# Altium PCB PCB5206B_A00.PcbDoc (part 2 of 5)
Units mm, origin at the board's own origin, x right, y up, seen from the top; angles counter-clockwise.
Board outline 115 x 60 mm, 6 copper layers (Top Layer, GND Layer 2, Signal Layer 3, Signal Layer 4, VCC Layer 5, Bottom Layer), stack 1.555 mm thick; 384 components, 267 nets, 1313 pads, 834 vias.
Unrouted connection lines stored in the file: 10.
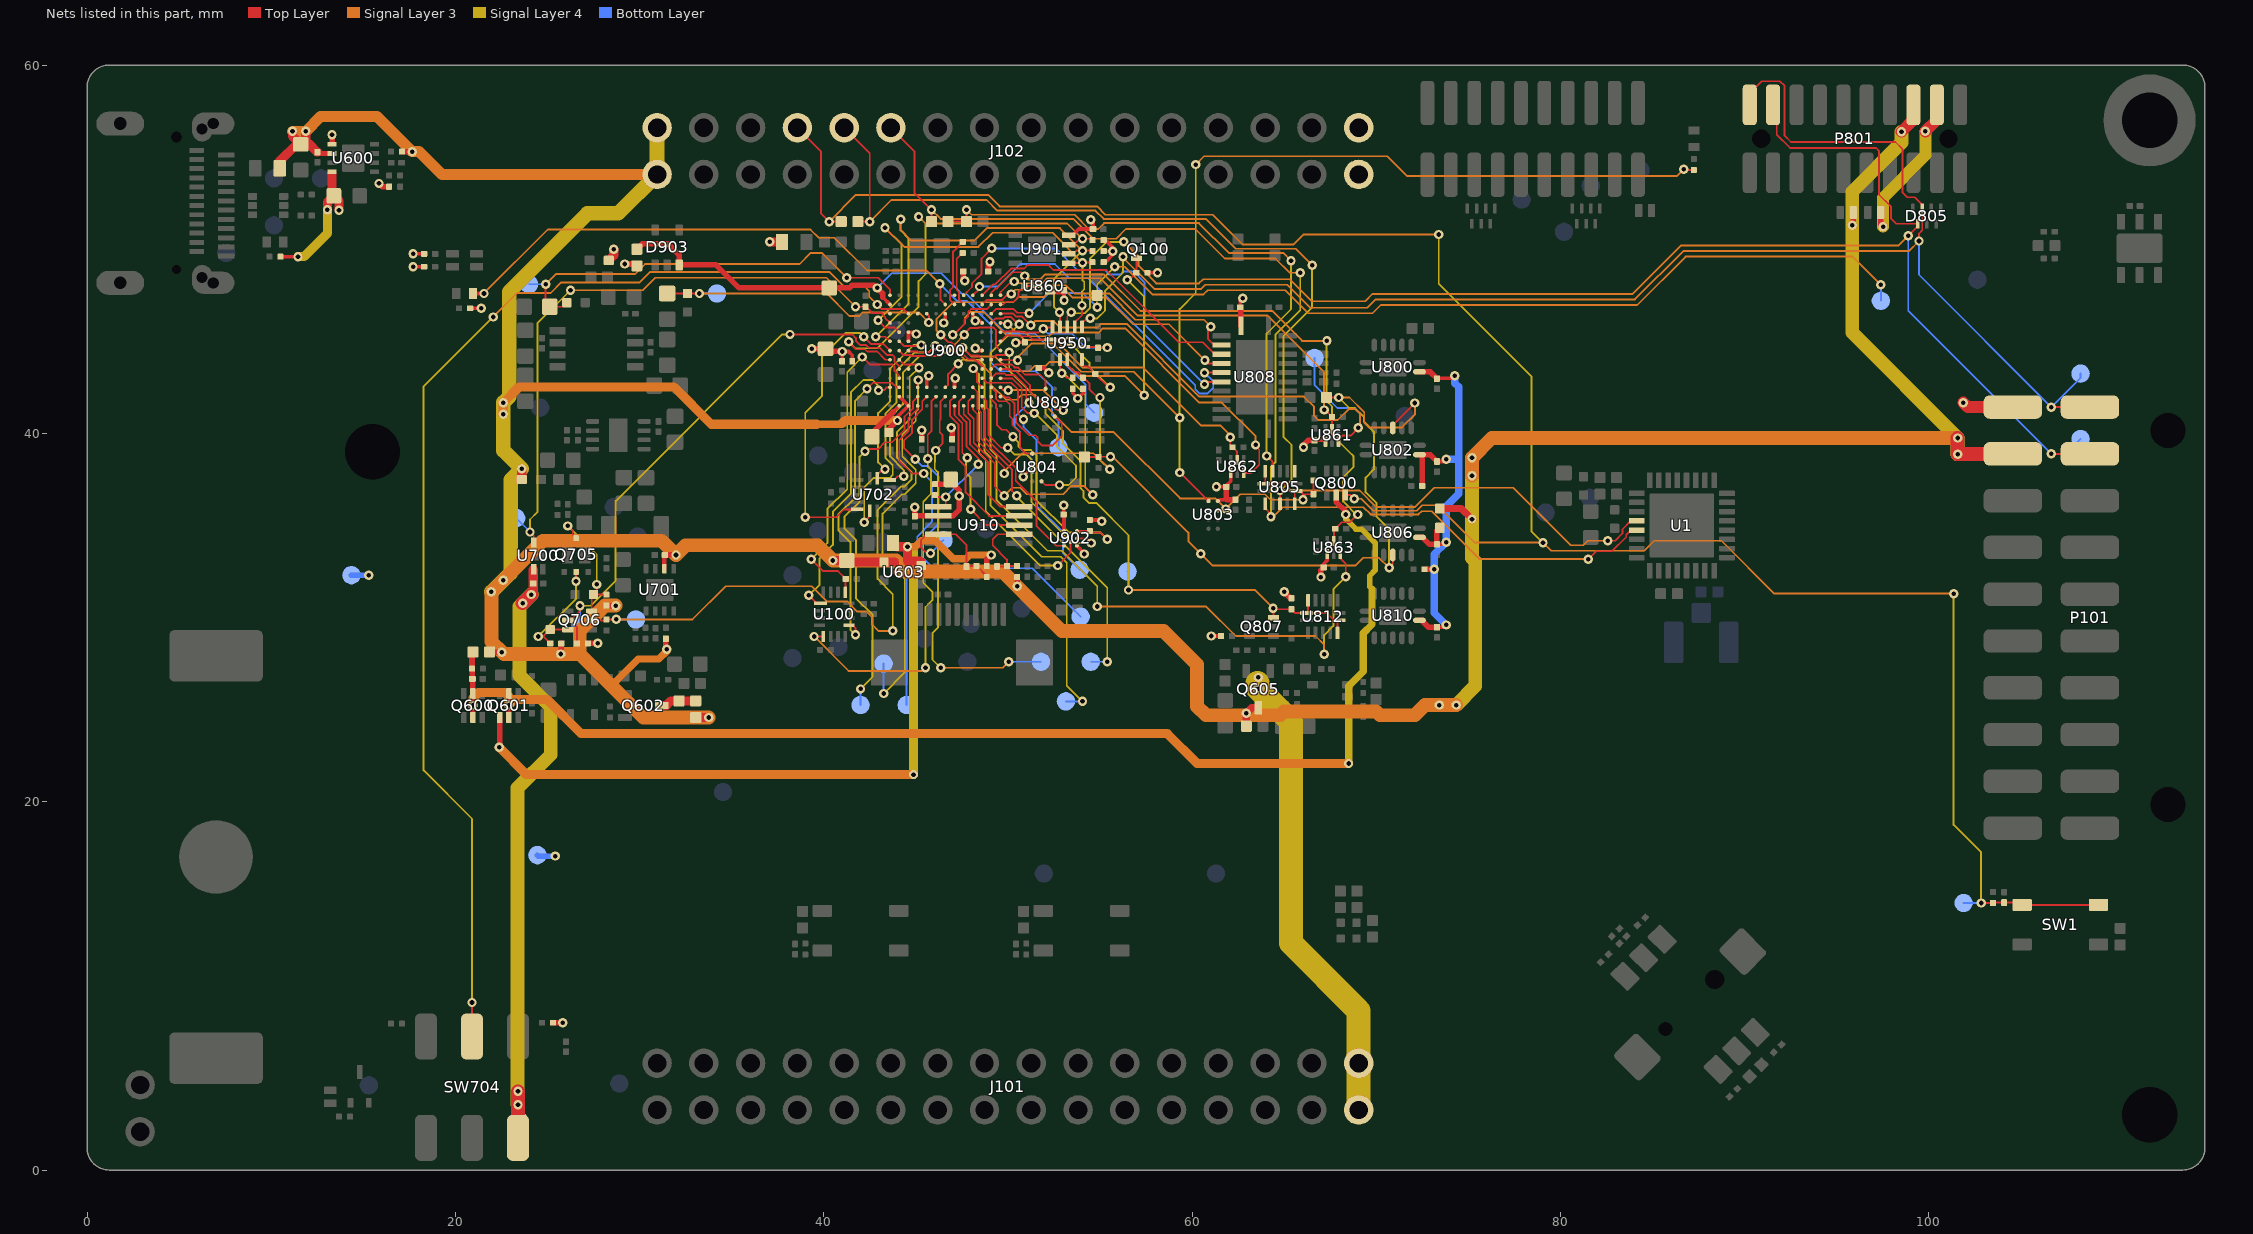
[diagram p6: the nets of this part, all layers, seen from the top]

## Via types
v1: diameter 0.508, hole 0.25, Top Layer to Bottom Layer, tented both sides, 834 vias

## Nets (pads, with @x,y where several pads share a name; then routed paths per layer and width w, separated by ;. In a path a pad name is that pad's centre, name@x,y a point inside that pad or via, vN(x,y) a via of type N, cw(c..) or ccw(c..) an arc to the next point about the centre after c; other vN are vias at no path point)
3V3: C607.1 C807.1 C808.1 C860.1 C862.1 C864.1 C866.1 C907.1 C908.1 C909.1 C910.1 C911.1 C914.1 C921.1 C922.1 C924.1 C925.1 C926.1 C927.1 C951.1 D807.1 J101.31 J101.32 J102.31 J102.32 L704.1 L900.1 P101.20 P801.3 R142.2 R601.2 R756.2 R793.2 R838.2 R840.2 R903.1 R906.2 R907.1 R908.1 R909.1 R912.1 R919.1 R920.1 R928.2 R951.1 R952.1 R982.1 TPJ600.1 TPJ950.1 U600.1 U600.4 U803.A2 U808.1 U860.1 U861.1 U862.1 U863.1 U900.C6 U900.C9 U900.G3 U900.H11 U900.J11 U900.K3 U900.L4 U900.L7 U901.8 U902.A1 U902.E3 U910.2 | length 87.6
  Top Layer w0.2: R903.1@10.5,49.6 v1(11.45,49.6) ; U600.1@13.3,55.7 13.3,55.85 ; v1(17.7,49.05) R919.1@18.3,49.05 ; v1(17.7,49.75) R920.1@18.3,49.75 ; R912.1@20.8,46.8 v1(21.4,46.8) ; C924.1@41,43.925 41,44.325 41.125,44.45 41.35,44.45 41.55,44.25 C925.1@41.55,43.925 ; U900.H11@44.6,45 U900.J11@44.6,45.5 44.925,45.5 v1(45.025,45.4) ; U900.C9@45.6,42.5 45.6,43.025 v1(45.7,43.125) ; v1(46.525,46) 46.55,46 46.6,46.05 U900.L7@46.6,46.5 ; U900.C6@47.1,42.5 47.1,42.925 v1@47.175,43 ; U900.L4@48.1,46.5 48.1,46.35 48.25,46.2 48.25,46.15 v1(48.225,46.125) 48.475,46.125 U900.K3@48.6,46 ; v1(48.225,44.625) 48.35,44.5 U900.G3@48.6,44.5 ; v1(50.425,44.925) 50.45,44.95 C911.1@50.925,44.95 ; C909.1@51.675,43.55 51.975,43.55 v1(52.225,43.3) ; U860.1@52.3,47.65 52.925,47.65 C862.1@53.05,47.775 v1(53.05,47.225) ; v1@52.9,36.1 53.025,35.975 C914.1@53.025,35.6 53.05,35.575 U902.A1@53.05,34.7 ; U901.8@53.3,50.75 53.5,50.75 53.85,51.1 C951.1@54.625,51.1 54.625,51.475 v1(54.5,51.6) ; R951.1@53.525,42.425 53.525,42.175 v1(53.8,41.9) 54.075,42.175 R952.1@54.075,42.425 ; U902.E3@53.75,33.9 54.15,33.5 v1(54.15,33.45) ; R906.2@54.45,35.3 55.025,35.3 v1(55.1,35.225) ; R908.1@55.2,49.3 55.3,49.3 55.725,49.725 v1@55.725,49.9 ; R907.1@55.2,49.9 v1(55.7,49.9) v1@55.725,49.9 ; R909.1@55.2,50.5 55.3,50.5 55.725,50.075 v1@55.725,49.9 ; R142.2@57.575,48.725 v1(58.125,48.725) ; v1(61.05,29) R838.2@61.575,29 ; v1(61.325,37.1) C860.1@61.85,37.1 61.85,37.15 62.1,37.4 U862.1@62.1,37.85 ; U803.A2@61.4,36.325 61.432,36.357 61.483,36.357 61.526,36.4 61.875,36.4 ; C808.1@62.625,46.85 62.625,47.225 v1(62.75,47.35) ; C864.1@66.65,39.625 67.175,39.625 U861.1@67.25,39.55 ; C866.1@67.15,32.725 67.15,32.925 67.35,33.125 U863.1@67.35,33.45
  Top Layer w0.25: 13.3,54.05 U600.4@13.3,54.2
  Top Layer w0.3: 13.3,55.85 v1(13.3,56.225) ; v1(15.85,53.575) 16.025,53.4 R601.2@16.4,53.4 ; R793.2@25.3,8 v1(25.825,8) ; R756.2@27.2,28.6 v1(27.725,28.6) ; v1(29.2,49.2) 29.75,49.2 R928.2@29.85,49.1 ; v1(39.35,44.6) C907.1@40.1,44.6 40.25,44.45 v1(41,44.45) v1@41.125,44.45 ; v1(44.95,36) C922.1@44.95,35.5 44.975,35.525 U910.2@46.225,35.525 47.025,35.525 47.35,35.85 47.35,36.925 46.825,37.45 46.625,37.25 R982.1@46.05,37.25 ; C927.1@45.325,39.675 v1(45.325,40.175) ; v1(46.925,40.3) 46.975,40.25 C926.1@46.975,39.675 ; C910.1@47.575,48.8 47.575,48.375 v1(47.65,48.3) ; C908.1@48.925,48.8 48.925,49.225 v1(49.025,49.325) ; C860.1@61.85,37.1 61.85,36.425 61.875,36.4 C807.1@62.35,36.4 ; C808.1@62.625,46.85 62.65,46.825 U808.1@62.65,45.845 ; v1(65,31.4) 65.35,31.05 R840.2@65.4,31.05 ; v1(66.05,39.25) 66.05,39.375 66.3,39.625 C864.1@66.65,39.625 ; v1(67,32.2) 67,32.575 C866.1@67.15,32.725 ; D807.1@97.4,52 97.4,51.35 v1(97.525,51.225)
  Top Layer w0.5: v1(13.05,52.15) 13.05,52.55 C607.1@13.4,52.9 ; 13.3,54.05 13.3,53 C607.1@13.4,52.9 ; v1(13.675,52.125) 13.675,52.625 C607.1@13.4,52.9 ; L704.1@28.325,49.4 28.6,49.675 v1(28.6,50) ; v1(37.06,50.4) L900.1@37.735,50.4
  Top Layer w0.635: v1(99.825,56.4) 100.445,57.02 P801.3@100.445,57.841 ; v1(101.875,41.675) 102.12,41.43 P101.20@104.57,41.43
  Signal Layer 4 w0.5: v1(11.45,49.6) 11.775,49.6 13.05,50.875 v1(13.05,52.15)
  Signal Layer 4 w0.635: v1(97.525,51.225) 97.525,52.8 99.825,55.1 v1(99.825,56.4)
  Signal Layer 4 w1.3: 63.55,26.45 63.55,26.175 65.375,24.35 65.375,12.325 69.05,8.65 J101.32@69.05,5.802 J101.31@69.05,3.262
  Bottom Layer w0.3: TPJ600.1@14.353,32.302 v1(15.3,32.3) ; TPJ950.1@24.452,17.1 24.502,17.05 v1(25.425,17.05)
  other v1: 63.6,26.125 63.6,26.75 53.025,36.1 47.35,36.6 47.15,43
3V6_SW: C608.1 L702.1 Q601.1 R639.2 U603.B1 | length 46.1
  Top Layer w0.2: U603.B1@44.55,32.65 44.55,33.075
  Top Layer w0.3: v1@22.4,22.95 Q601.1@22.4,24.575 ; R639.2@48.85,32.8 48.85,33.15 v1(49.1,33.4) v1@49,33.4
  Top Layer w0.5: L702.1@43.765,34.05 43.965,33.85 v1(44.55,33.85) 44.55,33.075 45.225,33.075 C608.1@45.3,33
  Signal Layer 3 w0.4: v1(44.55,33.85) 44.975,33.85 45.3,34.175 46.05,34.175 47.025,33.2 47.725,33.2 47.925,33.4 v1(49.1,33.4)
  Signal Layer 3 w0.5: v1(22.375,22.95) 23.85,21.475 v1(44.875,21.475)
  Signal Layer 4 w0.5: v1(44.55,33.85) 44.875,33.525 v1(44.875,21.475)
3V6_SW_SENSE: C641.1 R639.1 R640.2 TP923.1 U910.4 | length 7.4
  Top Layer w0.1: v1(45.8,33.5) 45.6,33.5 45.275,33.825 45.275,34.2 45.6,34.525 U910.4@46.225,34.525 47.175,34.525 47.75,33.95 C641.1@47.75,32.775 47.775,32.8 R640.2@48.3,32.8 48.85,32.25 R639.1@48.85,32.2
  Bottom Layer w0.1: v1(45.8,33.5) TP923.1@46.5,34.2
5V: C600.1 C609.1 C611.1 C702.1 C703.1 C901.1 D806.1 J102.1 J102.2 L600.2 L700.1 L800.1 P101.18 P801.5 Q605.3 R600.2 R622.2 R633.2 R680.1 R690.2 R700.2 R714.2 R755.2 U600.2 U603.A2 U603.B2 U701.2 U900.A11 U900.B12 | length 252
  Top Layer w0.2: C702.1@31.35,33.375 C702.1@31.375,33.4 ; 43.85,33.025 44.15,32.725 U603.B2@44.15,32.65 44.025,32.65 43.9,32.525 43.9,32.375 44.025,32.25 U603.A2@44.15,32.25 ; v1(44.002,40.702) 44.002,40.902 U900.A11@44.6,41.5 U900.B12@44.1,42
  Top Layer w0.25: C600.1@12.5,55.275 12.575,55.2 U600.2@13.3,55.2 ; U701.2@31.35,32.65 C702.1@31.35,33.375
  Top Layer w0.3: R600.2@17.1,55.3 v1(17.65,55.3) ; R622.2@21.85,28.125 v1(22.525,28.125) ; v1(25.725,28.025) 25.75,28.025 R714.2@25.75,28.6 ; R755.2@28.2,30.65 v1(28.7,30.65) ; C702.1@31.375,33.4 v1(31.975,33.4) ; R700.2@31.425,28.85 31.425,28.325 v1(31.475,28.275) ; C901.1@43.55,40.05 43.55,40.25 v1(44.002,40.702) ; v1(50.5,31.7) R633.2@50.5,32.2 ; v1(95.85,51.3) 95.9,51.35 D806.1@95.9,52
  Top Layer w0.4: R690.2@62.95,24.1 v1(62.95,24.8) 63.25,25.1 Q605.3@63.6,25.1 ; L800.1@73.45,35.925 74.625,35.925 v1(75.2,35.35)
  Top Layer w0.5: L600.2@10.465,54.4 10.465,54.79 11.375,55.7 C611.1@11.6,55.7 ; v1(11.15,56.4) 11.15,56.15 C611.1@11.6,55.7 ; v1(11.875,56.4) 11.875,55.975 C611.1@11.6,55.7 ; C600.1@12.5,55.275 12.075,55.7 C611.1@11.6,55.7 ; L700.1@23.6,37.5 v1(23.6,38.075) ; R680.1@33.05,24.575 v1(33.75,24.575) ; v1(40.5,33.1) C703.1@41.25,33.1 41.325,33.025 C609.1@43.275,33.025 43.85,33.025
  Top Layer w0.635: v1(98.525,56.375) 99.175,57.025 P801.5@99.175,57.841
  Top Layer w0.75: v1(101.575,39.75) v1(101.575,38.875) 101.59,38.89 P101.18@104.57,38.89
  Signal Layer 3 w0.4: 28.475,26.3 29.925,27.75 31.05,27.75 31.475,28.175 v1(31.475,28.275) ; 39.6,40.5 40.95,40.5 41,40.55
  Signal Layer 3 w0.5: v1(22.6,41.05) v1(22.6,41.675) 23.45,42.525 31.875,42.525 33.9,40.5 39.6,40.5 ; 41,40.55 41.152,40.702 v1(44.002,40.702)
  Signal Layer 3 w0.6: v1(11.15,56.4) v1(11.875,56.4) 12.675,57.2 15.75,57.2 v1(17.65,55.3) 18.025,55.3 19.263,54.062 J102.1@30.95,54.062
  Signal Layer 3 w0.75: v1(28.7,30.65) 28.125,30.65 26.75,29.275 26.75,28.025 ; v1(33.75,24.575) 30.2,24.575 28.475,26.3 26.75,28.025 ; v1(74.35,25.25) v1(73.425,25.25) 72.65,25.25 72.1,24.7 70.2,24.7 70,24.9 65,24.9 64.8,24.7 60.75,24.7 60.275,25.175 60.275,27.45 58.45,29.275 52.925,29.275 v1(50.5,31.7) 49.7,32.5 44.525,32.5 43.925,33.1 v1(40.5,33.1) 39.675,33.925 32.5,33.925 v1(31.975,33.4) 31.2,34.175 24.75,34.175 21.963,31.388 21.963,28.687 v1(22.525,28.125) 22.625,28.025 v1(25.725,28.025) 26.75,28.025 ; v1(75.2,37.7) v1(75.2,38.675) 76.275,39.75 v1(101.575,39.75) v1(101.575,38.875)
  Signal Layer 4 w0.75: v1(73.425,25.25) v1(74.35,25.25) 75.375,26.275 75.375,33.05 75.2,33.225 v1(75.2,35.35) v1(75.2,37.7) v1(75.2,38.675) ; v1(98.525,56.375) 98.525,55.8 95.85,53.125 v1(95.85,51.3) 95.85,45.475 v1(101.575,39.75) v1(101.575,38.875)
  Signal Layer 4 w0.8: v1(21.95,31.4) 21.975,31.4 v1(22.6,32.025) 23,32.425 23,37.475 v1(23.6,38.075) 22.6,39.075 v1(22.6,41.05) v1(22.6,41.675) 22.925,42 22.925,47.7 27.175,51.95 28.838,51.95 J102.1@30.95,54.062 J102.2@30.95,56.602
5V_BUF: Q602.3 R680.2 R681.2 | length 2
  Top Layer w0.5: Q602.3@31.2,25.225 31.45,25.225 31.7,25.475 R681.2@32.15,25.475 R680.2@33.05,25.475
5V_DH_SW: C803.1 C805.1 C809.1 C827.1 L800.2 R807.1 R808.1 U800.14 U802.14 U806.14 U810.14 | length 25.4
  Top Layer w0.2: C827.1@73.3,29.475 73.675,29.475 v1(73.8,29.6) ; C809.1@73.3,33.975 73.675,33.975 v1(73.8,34.1) ; C805.1@73.3,38.475 73.675,38.475 v1(73.8,38.6) ; C803.1@73.325,43 74.15,43 v1(74.275,43.125)
  Top Layer w0.3: U810.14@72.35,29.85 72.475,29.85 72.85,29.475 C827.1@73.3,29.475 ; U806.14@72.35,34.35 72.525,34.35 72.9,33.975 C809.1@73.3,33.975 73.3,34.725 L800.2@73.45,34.875 ; U802.14@72.35,38.85 U802.14@72.5,38.85 ; U800.14@72.35,43.35 72.925,43.35 C803.1@73.3,42.975 C803.1@73.325,43 ; R807.1@72.5,37.15 U802.14@72.5,38.85 ; R808.1@72.625,32.625 v1(73.15,32.625) ; C805.1@73.3,38.475 72.925,38.85 U802.14@72.5,38.85
  Bottom Layer w0.4: v1(73.8,29.6) 73.15,30.25 v1(73.15,32.625) 73.15,33.45 v1(73.8,34.1) 73.8,36.05 74.475,36.725 74.475,38.6 ; v1(73.8,38.6) 74.475,38.6 ; v1(74.275,43.125) 74.275,42.725 74.475,42.525 74.475,38.6
5V_SENSE: C635.1 R633.1 R634.2 U910.7 | length 4.4
  Top Layer w0.1: C635.1@49.4,32.775 49.925,32.775 R634.2@49.95,32.8 ; R633.1@50.5,32.8 R634.2@49.95,32.8 ; U910.7@50.625,34.525 49.444,34.525 49.182,34.263 49.182,33.918 49.95,33.15 R634.2@49.95,32.8
5V_SW: C610.1 Q600.2 Q600.5 Q601.2 Q601.5 Q800.5 R622.1 R623.2 | length 71.4
  Top Layer w0.3: C610.1@20.925,26.675 20.925,27.2 R623.2@20.9,27.225 20.9,28.075 R622.1@20.95,28.125 ; Q600.2@20.95,24.575 v1(20.95,25.225) 20.95,25.25 Q600.5@20.95,25.875 C610.1@20.95,26.65 ; Q601.2@22.9,24.575 v1(22.9,25.25) Q601.5@22.9,25.875 ; Q800.5@67.825,36.65 67.825,36.275 68.35,35.75 v1(68.35,35.6)
  Signal Layer 3 w0.5: v1(20.95,25.225) 20.95,25.626 21.249,25.925 22.675,25.925 22.9,25.7 v1(22.9,25.25) 23.2,25.55 24.975,25.55 26.825,23.7 58.65,23.7 60.275,22.075 v1(68.5,22.075)
  Signal Layer 4 w0.3: v1(68.35,35.6) 68.35,35.35 68.9,34.8 69.2,34.8 69.95,34.05 69.95,32.575 69.643,32.268 69.643,31.682 69.775,31.55
  Signal Layer 4 w0.4: v1(68.5,22.075) 68.5,26.275 69.3,27.075 69.3,29.15 69.775,29.625 69.775,31.55
#RESET: R805.2 R809.1 R810.2 U802.4 U806.11 | length 40
  Top Layer w0.1: R810.2@54.15,38.725 R809.1@54.925,38.725 54.938,38.737 v1(55.575,38.737) ; R805.2@67.3,41.95 v1(67.975,41.95) ; v1(70.7,32.7) 70.9,32.9 U806.11@70.9,33.4 ; U802.4@70.9,40.3 70.9,40.45 v1(72.1,41.65)
  Signal Layer 3 w0.1: v1@55.575,38.837 59.8,34.613 59.8,34.15 v1(60.475,33.475) 61.125,32.825 68.875,32.825 69.3,33.25 70.15,33.25 v1(70.7,32.7) ; v1(67.975,41.95) 68.55,41.95 69.35,41.15 69.35,40.575 69.6,40.325 71.4,40.325 72.1,41.025 v1(72.1,41.65)
  Signal Layer 4 w0.1: v1(67.975,41.95) 68.55,41.375 68.85,41.375 69.325,40.9 69.325,40.65 69.875,40.1 69.875,38.05 69.425,37.6 69.425,36.8 70.025,36.2 70.025,35.475 70.7,34.8 v1(70.7,32.7)
AEM_5V_#ENABLE: U900.L10
AEM_BYPASS_#EN: C709.1 Q705.2 Q706.6 R714.1 | length 6.6
  Top Layer w0.1: v1(24.5,28.975) 24.775,28.975 ; R714.1@25.15,28.6 24.775,28.975 ; Q706.6@26.1,29.35 C709.1@25.15,29.35 24.775,28.975 ; v1(26.55,31.975) Q705.2@26.55,32.488
  Signal Layer 4 w0.1: v1(24.5,28.975) 26.55,31.025 v1(26.55,31.975)
AEM_BYPASS_ENABLE: Q706.2 R754.2 TP720.1 U900.F12 | length 37.1
  Top Layer w0.1: Q706.2@27.4,29.85 28.15,29.85 R754.2@28.2,29.9 v1(28.725,29.9) ; U900.F12@44.1,44 44.35,43.75 45,43.75 v1(45.175,43.575)
  Signal Layer 3 w0.1: v1(28.725,29.9) 32.875,29.9 34.675,31.7 39.35,31.7 40.175,30.875 41.275,30.875 41.825,30.325 42.325,30.325 42.625,30.025 42.625,29.625 42.971,29.279 v1(43.75,29.279) ; v1@43.75,29.125 v1@43.75,29.154
  Signal Layer 4 w0.1: v1(43.75,29.279) 43.75,31.275 42.925,32.1 42.925,35.85 44.202,37.127 44.402,37.127 44.775,37.5 44.775,37.9 43.975,38.7 43.975,40.075 44.675,40.775 44.675,43.075 v1(45.175,43.575)
  Bottom Layer w0.1: v1(28.725,29.9) TP720.1@29.8,29.9
AEM_CALIBRATE0: U702.13 U900.G11 | length 14.9
  Top Layer w0.1: v1(42.2,35.175) 42.2,35.2 42.5,35.5 U702.13@42.5,35.79 ; U900.G11@44.6,44.5 44.65,44.45 45.099,44.45 45.14,44.409 45.709,44.409 v1(46.052,44.752) 46.075,44.775 v1@46.1,44.775
  Signal Layer 4 w0.1: v1(42.2,35.175) 42.2,37.075 42.7,37.575 43.575,37.575 43.75,37.75 43.75,38.275 43.35,38.675 43.35,41.075 43.95,41.675 43.95,43.4 44.95,44.4 45.7,44.4 v1(46.052,44.752)
AEM_CALIBRATE1: U702.5 U900.G12 | length 12.8
  Top Layer w0.1: U702.5@43.585,37.475 43.825,37.475 44.025,37.675 v1(44.35,37.675) ; U900.G12@44.1,44.5 44.35,44.25 44.704,44.25 44.752,44.202 46.327,44.202 v1(46.675,44.55)
  Signal Layer 4 w0.1: v1(44.35,37.675) 44.35,38 43.6,38.75 43.6,40.875 44.3,41.575 44.3,43.3 45.193,44.193 46.318,44.193 v1(46.675,44.55)
AEM_CALIBRATE2: U702.6 U900.H12 | length 10.2
  Top Layer w0.1: U702.6@42.9,37.56 42.9,37.75 43.2,38.05 v1(43.325,38.05) ; U900.H12@44.1,45 44.35,44.75 45.25,44.75 v1(45.302,44.802)
  Signal Layer 4 w0.1: v1(43.325,38.05) 42.95,38.425 42.95,41.1 43.6,41.75 43.6,43.525 44.877,44.802 v1(45.302,44.802)
AEM_CALIBRATE3: U702.12 U900.G13 | length 16.7
  Top Layer w0.1: v1(39,35.45) 40.675,35.45 41.1,35.875 U702.12@41.815,35.875 ; v1(42.175,45.25) 42.575,44.85 43.25,44.85 U900.G13@43.6,44.5
  Signal Layer 4 w0.1: v1(39,35.45) 39,41.125 39.9,42.025 39.9,44.175 41.175,45.45 41.975,45.45 v1(42.175,45.25)
AEM_CURRENT_HIGH_GAIN: C720.1 R764.2 TP706.1 U900.N13 | length 23.8
  Top Layer w0.1: v1(24.9,48.1) 24.9,47.1 R764.2@25.125,46.875 25.825,46.875 C720.1@26.05,47.1 ; v1(41.25,48.45) 42.95,48.45 43.6,47.8 U900.N13@43.6,47.5
  Signal Layer 3 w0.1: v1(24.9,48.1) 25.45,48.65 29.75,48.65 30.3,49.2 38.7,49.2 39.3,49.8 39.9,49.8 v1(41.25,48.45)
  Bottom Layer w0.1: TP706.1@24,48.1 v1(24.9,48.1)
AEM_CURRENT_LOW_GAIN: C724.1 R768.2 TP707.1 U900.L9 | length 16.5
  Top Layer w0.1: R768.2@31.5,47.6 C724.1@32.6,47.6 v1(33.25,47.6) ; U900.L9@45.6,46.5 45.725,46.375 45.725,46.05 v1(45.7,46.025)
  Signal Layer 3 w0.1: v1(33.25,47.6) 40.175,47.6 41.4,46.375 41.925,46.375 42.125,46.575 45.15,46.575 v1(45.7,46.025)
  Bottom Layer w0.1: v1(33.25,47.6) TP707.1@34.2,47.6
AEM_SENSE_#EN: C747.1 Q705.5 Q706.3 R755.1 | length 6.9
  Top Layer w0.1: v1(26.102,34.977) 26.369,34.709 26.369,34.494 Q705.5@26.55,34.313 ; Q706.3@27.4,30.35 27.4,31.15 C747.1@27.5,31.25 ; v1(27.675,31.8) 27.675,31.425 C747.1@27.5,31.25 ; R755.1@28.2,31.25 C747.1@27.5,31.25
  Signal Layer 4 w0.1: v1(26.102,34.977) 27.675,33.403 v1(27.675,31.8)
AEM_SENSE_ENABLE: Q706.5 R756.1 TP721.1 U900.E12 | length 30.7
  Top Layer w0.1: Q706.5@26.1,29.85 Q706.5@26.25,29.85 ; R756.1@26.6,28.6 26.6,29.5 Q706.5@26.25,29.85 ; v1(26.767,30.646) 26.767,30.367 Q706.5@26.25,29.85 ; v1(38.167,45.375) 41.55,45.375 41.75,45.175 41.75,45.025 41.975,44.8 42.3,44.8 42.45,44.65 43.05,44.65 43.45,44.25 43.75,44.25 43.85,44.15 43.85,43.9 43.85,43.896 43.996,43.75 44,43.75 44.1,43.65 U900.E12@44.1,43.5
  Signal Layer 4 w0.1: v1(26.767,30.646) 27.346,30.646 28.7,32 28.7,36.325 37.75,45.375 v1(38.167,45.375)
  Bottom Layer w0.1: v1(26.767,30.646) 26.767,29.633 TP721.1@26.8,29.6
AEM_SENSE_SELECT: U900.L13
AEM_SWITCH_POS: SW704.2 U900.L11 | length 66.4
  Top Layer w0.1: SW704.2@20.9,7.25 v1(20.9,9.1) ; v1(42.9,47) 43.15,46.75 44.35,46.75 U900.L11@44.6,46.5
  Signal Layer 3 w0.1: v1(22.05,46.325) 23.35,47.625 25.175,47.625 25.75,48.2 30,48.2 30.575,48.775 40.3,48.775 41.088,47.987 42.213,47.987 42.475,47.725 42.475,47.425 v1(42.9,47)
  Signal Layer 4 w0.1: v1(20.9,9.1) 20.9,19.075 18.275,21.7 18.275,42.55 v1(22.05,46.325)
AEM_VMCU: C708.1 SW704.4 TP709.1 U700.1 | length 35.6
  Top Layer w0.5: v1(24.125,31.25) 24.225,31.35 C708.1@24.225,31.85 U700.1@24.225,32.6
  Top Layer w0.75: SW704.4@23.4,1.75 v1(23.4,3.55) v1(23.4,4.275) ; v1(23.65,30.775) v1(24.125,31.25)
  Signal Layer 4 w0.75: v1(23.4,3.55) 23.375,3.575 23.375,4.275 23.375,20.75 25.175,22.55 25.175,25.15 23.475,26.85 23.475,30.6 v1(23.65,30.775) v1(24.125,31.25)
  Bottom Layer w0.635: v1(23.4,4.275) v1(23.4,3.55) 23.425,3.525 TP709.1@23.425,2.725
AEM_VMCU_ENABLE: R763.2 TP715.1 U700.4 U900.K13 | length 34.4
  Top Layer w0.1: v1(24.05,34.65) 24.25,34.45 U700.4@24.25,34.075 ; v1(41.725,46.875) R763.2@42.275,46.875 42.297,46.875 42.629,46.543 43.113,46.543 43.343,46.313 43.343,46.257 U900.K13@43.6,46
  Signal Layer 3 w0.1: v1(26.25,47.775) 30.175,47.775 30.85,48.45 40.15,48.45 v1(41.725,46.875)
  Signal Layer 4 w0.1: v1(24.05,34.65) 24.05,35.325 24.45,35.725 24.45,45.975 v1(26.25,47.775)
  Bottom Layer w0.1: TP715.1@23.3,35.4 v1(24.05,34.65)
BC_ADC_SPI_CIPO: U900.B6 U910.9 | length 9.1
  Top Layer w0.1: U900.B6@47.1,42 46.85,41.75 46.85,40.951 47.325,40.476 47.325,38.575 47.7,38.2 47.7,36.8 48.975,35.525 U910.9@50.625,35.525
BC_ADC_SPI_COPI: U900.A6 U910.8 | length 8.8
  Top Layer w0.1: U900.A6@47.1,41.5 47.1,40.984 47.525,40.559 47.525,38.95 v1(47.8,38.675) ; v1(47.975,35.875) 48.825,35.025 U910.8@50.625,35.025
  Signal Layer 4 w0.1: v1@47.725,38.5 47.725,37.85 47.975,37.6 v1(47.975,35.875)
BC_ADC_SPI_CS: R982.2 U900.B5 U910.1 | length 8.1
  Top Layer w0.1: R982.2@46.05,36.65 46.15,36.55 v1(46.625,36.55) 46.625,36.125 46.525,36.025 U910.1@46.225,36.025 ; U900.B5@47.6,42 47.35,41.75 47.35,41.017 47.75,40.617 47.75,39.3 48.4,38.65 v1(48.4,38.325)
  Bottom Layer w0.1: v1(46.625,36.55) 48.3,38.225 v1@48.3,38.3
BC_ADC_SPI_SCLK: U900.A5 U910.10 | length 7.3
  Top Layer w0.1: U900.A5@47.6,41.5 47.6,41.05 47.95,40.7 47.95,39.4 48.925,38.425 48.925,36.675 49.575,36.025 U910.10@50.625,36.025
BC_ADC_VREF: C919.1 D903.3 R928.1 TPJ905.1 U900.M13 | length 31.7
  Top Layer w0.2: 43.2,47.4 U900.M13@43.6,47
  Top Layer w0.3: R928.1@29.85,50 30.15,50.3 31.55,50.3 32.15,49.7 D903.3@32.15,49.15 34.15,49.15 35.4,47.9 C919.1@40.3,47.9 41.4,47.9 41.55,48.05 42.75,48.05 v1(42.9,47.9) 43.2,47.6 43.2,47.4
  Bottom Layer w0.1: v1(42.9,47.9) 43.7,48.7 46.375,48.7 47.49,47.585 47.74,47.585 49.9,45.425 51.45,45.425 54.225,42.65 54.225,41.579 TPJ905.1@54.678,41.126
BC_BUTTON_ENABLE: R981.1 U900.H1 U950.6 U950.12 | length 9.7
  Top Layer w0.1: U900.H1@49.6,45 49.932,45.332 50.574,45.332 50.626,45.28 51.17,45.28 51.35,45.1 U950.6@52.34,45.1 53.175,45.1 v1(53.275,45) ; U950.12@54.025,44.015 54.025,43.775 54.15,43.65 54.325,43.65 R981.1@54.75,43.225 55.475,42.5 v1(55.55,42.5)
  Signal Layer 4 w0.1: v1(53.275,45) 54.425,43.85 54.425,43.6 55.525,42.5 v1(55.55,42.5)
BC_DAC_OUT: U900.N6
BC_DBG_#RESET: LED903.1 TPJ956.1 U900.M7 | length 42.3
  Top Layer w0.1: v1(46.3,48.125) 46.35,48.075 46.35,47.25 U900.M7@46.6,47
  Top Layer w0.2: LED903.1@20.95,47.6 v1(21.55,47.6)
  Signal Layer 3 w0.1: v1(21.55,47.6) 25.025,51.075 39.275,51.075 39.725,50.625 40.575,50.625 42.35,48.85 45.575,48.85 v1(46.3,48.125)
  Bottom Layer w0.1: v1(46.3,48.125) 47.225,47.2 47.775,47.2 49.1,45.875 49.1,43.85 49.575,43.375 51.525,43.375 52.4,42.5 52.4,41 52.753,40.647 TPJ956.1@52.753,39.251
BC_DBG_TCK_SWCLK: TPJ954.1 U900.C10 | length 21.6
  Top Layer w0.1: U900.C10@45.1,42.5 45.1,42.775 45.05,42.825 45.05,42.85 45.1,42.9 v1(45.125,42.9) ; v1@45.225,42.852 v1@45.225,42.9
  Signal Layer 4 w0.1: v1(43.25,25.875) 44.4,27.025 44.4,32.1 43.2,33.3 43.2,35.65 44.25,36.7 44.4,36.7 45,37.3 45,38.025 44.262,38.763 44.262,39.937 45,40.675 45,41.175 45.125,41.3 v1(45.125,42.9)
  Bottom Layer w0.1: v1(43.25,25.875) 43.253,25.878 TPJ954.1@43.253,27.501
BC_DBG_TDO_SWO: TPJ955.1 U900.A10 | length 18.3
  Top Layer w0.1: U900.A10@45.1,41.5 45.1,41.342 44.595,40.837 44.595,40.129 44.1,39.634 44.1,38.525 44.8,37.825 v1(45.425,37.825)
  Bottom Layer w0.1: TPJ955.1@44.503,25.251 44.503,33.003 45.075,33.575 45.075,34.4 45.875,35.2 45.875,37.375 v1(45.425,37.825)
BC_DBG_TMS_SWDIO: TPJ953.1 U900.B10 | length 19.9
  Top Layer w0.1: v1(42.243,39.037) 42.356,39.15 42.95,39.15 43.325,39.525 43.708,39.525 44.395,40.212 44.395,40.92 44.85,41.375 44.85,41.75 U900.B10@45.1,42
  Signal Layer 4 w0.1: v1(42,26.125) 42.65,26.775 42.65,30.15 41.75,31.05 41.75,34.225 41.125,34.85 41.125,35.475 41.95,36.3 41.95,38.744 v1(42.243,39.037)
  Bottom Layer w0.1: v1(42,26.125) 42.001,26.124 TPJ953.1@42.001,25.251
BC_DISP_AVAILABLE: Q100.6 R142.1 U900.F3 | length 20.7
  Top Layer w0.1: v1(47.55,44.65) 47.975,44.225 48.375,44.225 U900.F3@48.6,44 ; v1(56.475,48.35) 56.6,48.35 R142.1@56.975,48.725 Q100.6@56.975,49.5
  Signal Layer 3 w0.1: v1(47.55,44.65) 48.025,44.175 49.325,44.175 50.125,43.375 51.15,43.375 51.45,43.675 52.05,43.675 52.25,43.875 53.1,43.875 53.85,43.125 56.35,43.125 v1(57.4,42.075)
  Signal Layer 4 w0.1: v1(56.475,48.35) 57.4,47.425 v1(57.4,42.075)
BC_DISP_COM: U900.E11
BC_DISP_CS: U100.9 U900.C12 | length 17.1
  Top Layer w0.1: U100.9@41.375,29.575 41.575,29.575 41.725,29.425 v1(41.725,29.075) ; v1(42.35,42.425) 42.675,42.75 43.704,42.75 43.954,42.5 U900.C12@44.1,42.5
  Signal Layer 4 w0.1: v1(41.725,29.075) 41.45,29.35 41.45,34.1 40.8,34.75 40.8,35.6 41.7,36.5 41.7,41.775 v1(42.35,42.425)
BC_DISP_PWR_ENABLE: R140.2 U100.13 U900.D12 | length 17.9
  Top Layer w0.1: v1(39.325,33.175) 39.975,32.525 40.775,32.525 R140.2@41.2,32.1 41.175,32.075 U100.13@41.175,31.375 ; v1(42.1,44.15) 42.5,43.75 43.714,43.75 43.85,43.614 43.85,43.604 43.85,43.396 44.1,43.146 U900.D12@44.1,43
  Signal Layer 4 w0.1: v1(39.325,33.175) 40.2,34.05 40.2,35.901 41.275,36.976 41.275,43.325 v1(42.1,44.15)
BC_DISP_SCLK: U100.1 U900.C13 | length 15.7
  Top Layer w0.1: v1(39.188,31.206) 39.619,30.775 U100.1@39.825,30.775 ; v1(42.975,42.35) 43.275,42.35 43.425,42.5 U900.C13@43.6,42.5
  Signal Layer 4 w0.1: v1(39.188,31.206) 39.775,31.793 39.775,33.225 40.5,33.95 40.5,35.75 41.475,36.725 41.475,42.225 42.15,42.9 42.65,42.9 42.925,42.625 v1@42.925,42.225
BC_DISP_SI: U100.5 U900.B8 | length 22.9
  Top Layer w0.1: v1(39.475,28.975) U100.5@39.975,28.975 ; v1(45.65,38.625) 45.65,39.925 45.85,40.125 45.85,41.75 U900.B8@46.1,42
  Signal Layer 3 w0.1: v1(39.475,28.975) 41.35,27.1 45.35,27.1 v1(45.525,27.275)
  Signal Layer 4 w0.1: v1(45.525,27.275) 45.525,30.575 45.9,30.95 45.9,31.4 45.4,31.9 45.4,36.3 45.825,36.725 45.825,38.025 45.65,38.2 v1(45.65,38.625)
BC_I2C_EXP_ENABLE: R950.1 U900.J1 U950.5 U950.13 | length 8.2
  Top Layer w0.1: U900.J1@49.6,45.5 49.6,45.532 50.656,45.532 50.708,45.48 51.68,45.48 51.95,45.75 52.39,45.75 U950.5@52.425,45.785 ; U950.13@54.11,44.7 54.85,44.7 R950.1@54.9,44.65 v1@55.4,44.65
  Bottom Layer w0.1: v1(51.925,45.675) 52.175,45.425 53.475,45.425 54.238,44.662 v1(55.4,44.662)
BC_I2C_EXP_SCL: D805.5 P101.17 P801.17 TPJ651.1 U950.3 | length 85.9
  Top Layer w0.1: U950.3@53.225,45.785 53.225,46.35 v1(53.45,46.575) ; P801.17@91.555,57.841 91.75,57.647 91.75,56.225 92.475,55.5 97.15,55.5 97.3,55.35 97.3,52.975 97.95,52.325 97.95,51.675 98.24,51.385 D805.5@99.4,51.385 99.4,51.25 v1(98.892,50.742) ; v1(106.66,38.89) P101.17@108.76,38.89
  Signal Layer 3 w0.1: v1(56.3,50.4) 57.1,49.6 57.1,49.1 58.05,48.15 60.375,48.15 60.6,48.375 65.3,48.375 66.5,47.175 69.4,47.175 69.8,47.575 83.925,47.575 86.55,50.2 98.35,50.2 v1(98.892,50.742)
  Signal Layer 4 w0.1: v1(53.45,46.575) 53.5,46.525 54.175,46.525 54.45,46.8 54.45,49.475 55.375,50.4 v1(56.3,50.4)
  Bottom Layer w0.1: v1(98.892,50.742) 98.892,46.658 v1(106.66,38.89) 107.441,38.89 TPJ651.1@108.25,39.7
BC_I2C_EXP_SDA: D805.3 P101.19 P801.19 TPJ650.1 U950.1 | length 85.8
  Top Layer w0.1: U950.1@54.025,45.785 54.025,45.975 54.3,46.25 v1(54.475,46.25) ; P801.19@90.285,57.841 90.285,58.485 90.925,59.125 91.925,59.125 92.175,58.875 92.175,56.175 92.525,55.825 98.2,55.825 98.575,55.45 98.575,53.1 98.85,52.825 99.25,52.825 99.65,52.425 D805.3@99.65,52.215 99.65,51.025 99.475,50.85 v1(99.475,50.45) ; v1(106.66,41.43) P101.19@108.76,41.43
  Signal Layer 3 w0.1: v1(56.25,49.6) 56.25,49.55 57.95,47.85 60.499,47.85 60.724,48.075 65.176,48.075 66.426,46.825 69.525,46.825 69.975,47.275 84.049,47.275 86.674,49.9 98.925,49.9 v1(99.475,50.45)
  Signal Layer 4 w0.1: v1(54.475,46.25) 54.85,46.25 55.275,46.675 55.275,47.75 56.25,48.725 v1(56.25,49.6)
  Bottom Layer w0.1: v1(99.475,50.45) 99.475,48.615 v1(106.66,41.43) 108.25,43.02 TPJ650.1@108.25,43.248
BC_SPI_CIPO: U900.B3 U902.C3 | length 12.5
  Top Layer w0.1: U900.B3@48.6,42 48.85,41.75 48.85,41.396 48.95,41.296 48.95,39.9 49.625,39.225 v1(50,39.225) ; U902.C3@53.75,34.3 54.275,34.3 v1(54.525,34.05)
  Signal Layer 4 w0.1: v1(50,39.225) 50.375,38.85 51.025,38.85 51.275,38.6 51.275,36.275 53.5,34.05 v1(54.525,34.05)
BC_SPI_COPI: U900.C3 U902.D2 | length 15.9
  Top Layer w0.1: v1(48.125,43.525) 48.325,43.325 48.325,42.775 U900.C3@48.6,42.5 ; v1(52.7,32.825) 53.4,33.525 U902.D2@53.4,34.1
  Signal Layer 4 w0.1: v1(48.125,43.525) 48.425,43.225 48.425,38.95 48.8,38.575 48.8,35.775 51.75,32.825 v1(52.7,32.825)
BC_SPI_CS: R906.1 U900.B2 U902.A3 | length 13.6
  Top Layer w0.1: U900.B2@49.1,42 49.1,41.854 49.35,41.604 49.35,41.396 49.4,41.346 49.4,40.475 49.675,40.2 49.9,40.2 v1(50.275,39.825) ; U902.A3@53.75,34.7 R906.1@54.45,34.7 54.525,34.625 55.025,34.625 v1(55.4,34.25)
  Signal Layer 4 w0.1: v1(50.275,39.825) 50.575,39.525 50.575,39.3 50.775,39.1 51.25,39.1 51.55,38.8 51.55,36.375 53.3,34.625 55.025,34.625 v1(55.4,34.25)
BC_SPI_SCLK: U900.A3 U902.E1 | length 9.7
  Top Layer w0.1: U900.A3@48.6,41.5 48.6,41.364 48.75,41.214 48.75,39.8 50.425,38.125 50.425,37.431 51.55,36.306 51.55,34.975 52.625,33.9 U902.E1@53.05,33.9
BC_TRACECLK: TPJ957.1 U900.B7 | length 21
  Top Layer w0.1: v1(46.075,39.075) 46.443,39.443 46.443,39.924 46.3,40.067 46.3,40.725 46.35,40.775 46.35,41.75 U900.B7@46.6,42
  Signal Layer 3 w0.1: v1(46.35,27.275) 49.731,27.275 v1(50.053,27.597)
  Signal Layer 4 w0.1: v1(46.075,39.075) 46.05,39.05 46.05,38.456 46.032,38.438 46.032,38.068 46.2,37.9 46.2,29.45 45.9,29.15 45.9,27.725 v1(46.35,27.275)
  Bottom Layer w0.1: v1(50.053,27.597) 50.051,27.599 TPJ957.1@51.799,27.599
BC_TRACED0: TPJ958.1 U900.C7 | length 25.2
  Top Layer w0.1: U900.C7@46.6,42.5 46.75,42.65 46.75,43.225 v1(47.3,43.775)
  Signal Layer 4 w0.1: v1(47.3,43.775) 47.525,44 48.45,44 48.725,43.725 48.725,39.025 49.05,38.7 49.05,36.1 51.85,33.3 52.875,33.3 53.2,32.975 53.2,26.3 v1(54.05,25.45)
  Bottom Layer w0.1: TPJ958.1@53.15,25.45 v1(54.05,25.45)
BC_TRACED1: TPJ959.1 U900.C4 | length 18.8
  Top Layer w0.1: U900.C4@48.1,42.5 48.35,42.25 48.35,41.331 48.55,41.131 48.55,39.7 50.225,38.025 50.225,36.875 v1(50.475,36.625)
  Signal Layer 4 w0.1: v1(50.475,36.625) 50.475,36.55 55.4,31.625 v1(55.4,27.598)
  Bottom Layer w0.1: TPJ959.1@54.499,27.599 55.398,27.599 v1(55.4,27.598)
BC_TRACED2: TPJ960.1 U900.D3 | length 13.5
  Top Layer w0.1: U900.D3@48.6,43 48.85,42.75 50.192,42.75 50.55,42.392 50.55,41.075 v1@50.923,40.702
  Bottom Layer w0.1: v1(50.85,40.775) 50.85,40.35 51.55,39.65 51.55,36.075 53,34.625 53,33.497 TPJ960.1@53.899,32.598
BC_TRACED3: TPJ961.1 U900.B9 | length 20.6
  Top Layer w0.1: v1@45.003,38.578 44.35,39.231 44.35,39.601 44.795,40.047 44.795,40.754 45.35,41.309 45.35,41.75 U900.B9@45.6,42
  Bottom Layer w0.1: v1(44.978,38.603) 45.356,38.225 45.675,38.225 46.225,37.675 46.225,35.075 45.325,34.175 45.325,33.3 45.95,32.675 51.325,32.675 TPJ961.1@53.95,30.05
BC_UIF_BUTTON0: R951.2 U900.B4 U950.9 | length 20.6
  Top Layer w0.1: U900.B4@48.1,42 47.85,41.75 47.85,41.1 48.15,40.8 48.15,39.5 49.3,38.35 49.3,37.125 v1(49.8,36.625) ; U950.9@52.825,44.015 52.825,43.375 v1(52.925,43.275) 52.937,43.275 53.187,43.025 R951.2@53.525,43.025
  Signal Layer 3 w0.1: v1(49.8,36.625) 50.225,37.05 50.675,37.05 51.025,36.7 53,36.7 53.45,37.15 54.125,37.15 v1(54.6,36.675)
  Signal Layer 4 w0.1: v1(52.925,43.275) 53.025,43.275 54.2,42.1 54.2,37.075 v1(54.6,36.675)
BC_UIF_BUTTON1: R952.2 U900.A4 U950.10 | length 18.2
  Top Layer w0.1: U900.A4@48.1,41.5 48.1,41.298 48.35,41.048 48.35,39.6 49.8,38.15 v1(49.8,37.825) ; U950.10@53.225,44.015 53.225,43.725 53.605,43.345 53.724,43.345 53.744,43.325 53.825,43.325 54.425,42.725 54.425,42.4 54.875,41.95 v1(55,41.95)
  Signal Layer 3 w0.1: v1@49.85,37.725 49.85,38 50.775,38.925 54.65,38.925 v1(55.525,38.05)
  Signal Layer 4 w0.1: v1(55,41.95) 55,38.575 v1(55.525,38.05)
BC_VCOM_CTS: U863.3 U900.K2 | length 40.6
  Top Layer w0.1: U900.K2@49.1,46 49.35,46.25 49.769,46.25 49.837,46.318 50.186,46.318 50.625,45.879 v1(50.625,45.925) ; v1@50.6,45.825 50.65,45.775 v1@50.675,45.8 ; U863.3@68.05,33.45 68.05,33.225 68.35,32.925 v1(68.35,32.225)
  Signal Layer 3 w0.1: v1(54.85,30.6) 60.775,30.6 62.375,29 66.706,29 67.175,28.531 v1(67.175,28)
  Signal Layer 4 w0.1: v1(50.625,45.925) 49.05,44.35 49.05,39.15 49.375,38.825 49.375,36.4 52.15,33.625 52.925,33.625 54.85,31.7 v1(54.85,30.6) ; v1(67.175,28) 67.175,29.05 67.675,29.55 67.675,31.55 v1(68.35,32.225)
BC_VCOM_CTS_DIR: R853.2 U863.5 U900.N2 | length 33.7
  Top Layer w0.1: U900.N2@49.1,47.5 49.1,47.642 49.333,47.875 49.4,47.875 50.275,48.75 50.725,48.75 v1(50.925,48.55) ; U863.5@67.7,34.15 67.7,34.75 R853.2@67.775,34.825 68.125,35.175 68.575,35.175 v1(69,35.6)
  Signal Layer 3 w0.1: v1(50.925,48.55) 51.118,48.357 51.732,48.357 52,48.625 55.225,48.625 57.2,46.65 64.35,46.65 65.975,45.025 v1(67.325,45.025)
  Signal Layer 4 w0.1: v1(67.325,45.025) 67.3,45 67.3,41.767 67.6,41.467 67.6,39.925 68.507,39.018 68.513,39.018 68.743,38.788 68.743,38.782 68.775,38.75 68.775,38.2 68.2,37.625 68.2,36.306 69,35.506 v1(69,35.6)
BC_VCOM_ENABLE: Q807.3 R840.1 TP930.1 U812.5 U812.6 U812.12 U812.13 U900.F2 | length 32.1
  Top Layer w0.1: U900.F2@49.1,44 49.35,44.25 49.8,44.25 49.95,44.4 v1(50.075,44.4) ; v1(64.4,30.5) v1@64.425,30.475 ; Q807.3@64.55,30 Q807.3@64.425,30 v1@64.425,30.475 ; U812.12@66.3,30.935 66.3,30.335 U812.13@66.215,30.25 ; U812.5@67.9,29.165 U812.6@67.9,29.85 ; U812.6@67.985,29.85 U812.6@67.9,29.85 ; v1@64.425,30.475 64.45,30.45 R840.1@65.4,30.45 65.6,30.25 U812.13@66.215,30.25 ; U812.13@66.215,30.25 67.325,30.25 67.725,29.85 U812.6@67.9,29.85
  Signal Layer 3 w0.1: v1(56.55,31.5) 63.4,31.5 v1(64.4,30.5)
  Signal Layer 4 w0.1: v1(50.075,44.4) 50.075,43.4 52.05,41.425 52.05,41.075 53,40.125 53,39.45 53.95,38.5 53.95,37.025 54.1,36.875 54.1,36.525 54.4,36.225 54.8,36.225 56.55,34.475 v1(56.55,31.5)
  Bottom Layer w0.1: TP930.1@56.5,32.5 56.55,32.45 v1(56.55,31.5)
BC_VCOM_RTS: U862.3 U900.K1 | length 19.4
  Top Layer w0.1: U900.K1@49.6,46 49.925,46 v1(50,45.925) ; U862.3@62.8,37.85 63.2,37.85 63.65,38.3 63.65,39.1 63.45,39.3 v1(63.45,39.375)
  Signal Layer 3 w0.1: v1(50,45.925) 50.4,45.525 50.899,45.525 51.149,45.275 52.225,45.275 52.425,45.475 54.925,45.475 55.15,45.7 56.375,45.7 60.4,41.675 61.625,41.675 63.45,39.85 v1(63.45,39.375)
BC_VCOM_RTS_DIR: R852.2 U862.5 U900.M2 | length 23.1
  Top Layer w0.1: v1(47,45.35) 47.056,45.35 47.64,45.935 47.64,46.14 47.85,46.35 47.85,46.604 47.996,46.75 48.85,46.75 U900.M2@49.1,47 ; v1(62.075,39.8) 62.075,39.375 R852.2@62.2,39.25 62.45,39 U862.5@62.45,38.55
  Signal Layer 3 w0.1: v1(47,45.35) 47.056,45.35 47.675,45.969 47.675,46.3 47.975,46.6 48.675,46.6 49.95,45.325 50.65,45.325 50.9,45.075 52.575,45.075 54.075,43.575 57.35,43.575 60.5,40.425 61.556,40.425 62.075,39.906 v1(62.075,39.8)
BC_VCOM_RXD: R882.2 TPJ606.1 U900.L2 | length 55.6
  Top Layer w0.1: U900.L2@49.1,46.5 49.35,46.75 50.319,46.75 50.512,46.557 51.118,46.557 v1(51.15,46.525) ; v1(54.85,46.85) R882.2@54.85,47.5
  Signal Layer 3 w0.1: v1(55.8,49.05) 56.35,49.05 57.85,47.55 60.624,47.55 60.849,47.775 65.051,47.775 66.301,46.525 69.8,46.525 70.25,46.975 84.174,46.975 86.799,49.6 95.875,49.6 v1(97.4,48.075)
  Signal Layer 4 w0.1: v1(54.85,46.85) 54.85,48.1 v1(55.8,49.05)
  Bottom Layer w0.1: v1(51.15,46.525) 52.25,47.625 54.075,47.625 v1(54.85,46.85) ; TPJ606.1@97.404,47.202 v1@97.404,48.075
BC_VCOM_RXD_DIR: R850.2 U860.5 U900.M1 | length 2.6
  Top Layer w0.1: U900.M1@49.6,47 49.75,47 49.9,47.15 50.319,47.15 50.375,47.206 50.375,47.219 50.568,47.412 50.568,47.668 R850.2@50.9,48 U860.5@51.6,48
BC_VCOM_TXD: TPJ607.1 U861.3 U900.L1 | length 30.6
  Top Layer w0.1: U900.L1@49.6,46.5 49.618,46.518 50.269,46.518 50.429,46.357 50.762,46.357 51.244,45.875 v1(51.25,45.875) ; U861.3@67.95,39.55 67.95,39.675 68.158,39.882 68.607,39.882 v1(69.025,40.3)
  Signal Layer 3 w0.1: v1(51.25,45.875) 51.475,46.1 52.5,46.1 52.85,45.75 54.85,45.75 55.05,45.95 56.45,45.95 60.4,42 66.075,42 66.625,41.45 66.625,40.95 66.85,40.725 67.9,40.725 68.5,41.325 68.875,41.325 69.125,41.075 69.125,40.4 v1(69.025,40.3)
  Bottom Layer w0.1: TPJ607.1@66.653,44.101 66.653,42.622 67.9,41.375 68.825,41.375 69.125,41.075 69.125,40.4 v1(69.025,40.3)
BC_VCOM_TXD_DIR: R851.2 U861.5 U900.N1 | length 23.6
  Top Layer w0.1: U900.N1@49.6,47.5 49.6,47.675 50.175,48.25 v1(50.35,48.25) ; v1(67.175,41.275) 67.225,41.275 R851.2@67.6,40.9 U861.5@67.6,40.25
  Signal Layer 3 w0.1: v1(50.35,48.25) 50.35,48.189 50.318,48.157 51.857,48.157 52.125,48.425 55.025,48.425 57.05,46.4 64.1,46.4 67.175,43.325 v1(67.175,41.275)
BOARD_ID_SCL: R907.2 U900.H13 U901.6 U950.4 | length 26.1
  Top Layer w0.1: v1(42.825,45.25) 43.35,45.25 U900.H13@43.6,45 ; v1@52.8,46.75 52.825,46.725 U950.4@52.825,45.785 ; U901.6@53.3,49.75 53.55,49.75 53.725,49.925 v1(54.05,49.925) 54.575,49.925 R907.2@54.6,49.9
  Signal Layer 3 w0.1: v1(44.175,51.625) 44.175,51.05 44.75,50.475 48.175,50.475 48.85,51.15 52.825,51.15 v1(54.05,49.925)
  Signal Layer 4 w0.1: v1(42.825,45.25) 44.6,47.025 44.6,50.6 44.175,51.025 v1(44.175,51.625) ; v1(52.8,46.575) 52.5,46.875 52.5,48.375 v1(54.05,49.925)
BOARD_ID_SDA: R908.2 U900.J12 U901.5 U950.2 | length 24.8
  Top Layer w0.1: v1(42.95,46.15) 43.35,45.75 43.85,45.75 U900.J12@44.1,45.5 ; U901.5@53.3,49.25 54.025,49.25 v1(54.05,49.275) 54.575,49.275 R908.2@54.6,49.3 ; U950.2@53.625,45.785 53.625,46.025 54.025,46.425 v1(54.025,46.95)
  Signal Layer 3 w0.1: v1(43.325,51.175) 44.375,50.125 48.4,50.125 49.175,50.9 52.425,50.9 v1(54.05,49.275)
  Signal Layer 4 w0.1: v1(42.95,46.15) 44.225,47.425 44.225,50.275 v1(43.325,51.175) ; v1(54.025,46.95) 54.025,47.7 54.15,47.825 54.15,48.225 54.05,48.325 v1(54.05,49.275) v1@54.175,49.15 ; v1@54.125,46.925 v1@54.175,46.975
BOARD_ID_WP: R909.2 U900.F13 U901.7 | length 23.5
  Top Layer w0.1: v1(41.35,44.975) 41.75,44.575 42.242,44.575 42.367,44.45 42.9,44.45 43.35,44 U900.F13@43.6,44 ; U901.7@53.3,50.25 53.575,50.25 v1@53.9,50.575 ; v1(54.05,50.575) 54.525,50.575 R909.2@54.6,50.5
  Signal Layer 3 w0.1: v1(45.15,51.775) 45.525,51.4 53.225,51.4 v1(54.05,50.575)
  Signal Layer 4 w0.1: v1(41.35,44.975) 41.7,44.625 42.9,44.625 45.15,46.875 45.15,48.275 45.525,48.65 45.525,51.4 v1(45.15,51.775)
BOARD_VER0: R930.1 U900.M5 | length 3.1
  Top Layer w0.1: R930.1@47.55,49.8 47.225,49.475 47.225,47.8 47.35,47.675 47.35,47.25 U900.M5@47.6,47
BOARD_VER1: R931.1 U900.M6 | length 3.8
  Top Layer w0.1: U900.M6@47.1,47 46.85,47.25 46.85,47.775 47.025,47.95 47.025,49.875 R931.1@47.55,50.4
DBG_VREGO: C902.1 U900.A12 | length 2.4
  Top Layer w0.1: C902.1@42.55,39.875 42.6,39.825 C902.1@42.625,39.825
  Top Layer w0.2: 43.778,41.178 U900.A12@44.1,41.5
  Top Layer w0.3: C902.1@42.625,39.825 42.625,40.025 43.778,41.178
DEBUG_#RESET_C2CKPS: C8.1 J102.8 Q800.6 R9.2 R301.2 SW1.1 SW1.2 TP154.1 | length 121.3
  Top Layer w0.1: J102.8@38.57,56.602 39.85,55.322 39.85,51.95 v1(40.3,51.5) R301.2@40.95,51.5 ; Q800.6@68.325,36.65 68.6,36.65 v1(68.8,36.45) ; v1(102.85,14.5) R9.2@103.5,14.5 103.525,14.525 C8.1@104.1,14.525 104.95,14.525 SW1.1@105.075,14.4 SW1.2@109.225,14.4
  Signal Layer 3 w0.1: v1(40.3,51.5) 41.75,52.95 48.925,52.95 49.55,52.325 54.843,52.325 55.293,51.875 61.125,51.875 62.75,50.25 65.5,50.25 66.05,50.8 v1(73.4,50.8) ; v1(68.8,36.45) 69.2,36.45 69.85,35.8 72.212,35.8 72.512,36.1 73.325,36.1 75.356,34.069 v1(79.056,34.069) 79.5,33.625 84.55,33.625 85.1,34.175 88.75,34.175 91.625,31.3 v1(101.357,31.3)
  Signal Layer 4 w0.1: v1(73.4,50.8) 73.4,48.125 78.425,43.1 78.425,34.7 v1(79.056,34.069) ; v1(101.357,31.3) 101.357,18.743 102.85,17.25 v1(102.85,14.5)
  Bottom Layer w0.1: TP154.1@101.9,14.5 v1(102.85,14.5)
DEBUG_#RESET_IN: U808.7 U900.N5 | length 20.3
  Top Layer w0.1: U900.N5@47.6,47.5 48.05,47.95 48.05,48.15 48.575,48.675 48.575,49.5 v1(49.125,50.05) ; v1(60.675,42.675) 60.675,42.7 60.775,42.8 U808.7@61.605,42.8
  Bottom Layer w0.1: v1(49.125,50.05) 52.6,50.05 53.775,48.875 55.25,48.875 55.5,48.625 56.1,48.625 56.275,48.8 56.825,48.8 57.413,48.212 57.413,45.938 v1(60.675,42.675)
DEBUG_DH_SW_ENABLE: R900.1 U803.A1 U900.F1 | length 59
  Top Layer w0.1: U900.F1@49.6,44 50.05,44 50.075,43.975 v1(50.525,43.975) ; v1(59.325,37.875) 59.35,37.875 U803.A1@60.9,36.325 ; v1@86.7,54.3 R900.1@87.25,54.3
  Signal Layer 3 w0.1: v1(50.525,43.975) 50.525,44.131 51.269,44.875 52.45,44.875 53.975,43.35 56.825,43.35 v1(59.325,40.85) ; v1(60.2,54.6) 60.65,55.05 70.6,55.05 71.675,53.975 86.325,53.975 v1(86.7,54.35)
  Signal Layer 4 w0.1: v1(59.325,37.875) 59.325,39.9 59.325,46.75 60.2,47.625 v1(60.2,54.6)
DEBUG_MCU_SW_ENABLE: R814.2 R815.2 U803.B2 U805.5 U805.6 U805.12 U805.13 U900.G1 | length 34.3
  Top Layer w0.1: v1(47.625,45.35) 47.625,45.4 47.957,45.732 48.388,45.732 48.406,45.75 49.225,45.75 49.35,45.625 49.35,44.75 U900.G1@49.6,44.5 ; U803.B2@61.4,35.825 61.825,35.825 v1(61.825,35.9) ; U805.12@63.975,37.955 63.975,37.355 U805.13@63.89,37.27 64.47,37.27 64.525,37.325 64.95,37.325 65.405,36.87 U805.6@65.66,36.87 ; U805.5@65.575,36.185 65.575,36.785 U805.6@65.66,36.87 ; R815.2@66.6,37.45 R814.2@66.6,36.7 66.15,36.7 ; U805.6@65.66,36.87 65.88,36.87 66.05,36.7 ; v1@66.025,36.575 66.025,36.675 66.05,36.7 ; v1@66.025,36.575 v1(66.025,36.4) 66.15,36.525 66.15,36.7 ; v1@66.025,36.575 66.15,36.7 ; 66.05,36.7 66.15,36.7
  Signal Layer 3 w0.1: v1(47.625,45.35) 47.1,44.825 47.1,44.5 47.375,44.225 47.45,44.225 47.725,43.95 48.375,43.95 49.075,43.25 49.075,42.65 49.9,41.825 50.475,41.825 50.75,42.1 51.45,42.1 53.475,40.075 55.75,40.075 59.35,36.475 61.25,36.475 v1(61.825,35.9) 62.625,36.7 63.961,36.7 64.261,36.4 v1(66.025,36.4)
DEBUG_RESET_#OE: U804.A1 U900.D1 | length 9.8
  Top Layer w0.1: U900.D1@49.6,43 49.625,42.975 50.25,42.975 50.75,42.475 50.75,41.425 51.075,41.1 v1(51.425,41.1) ; U804.A1@51.825,37.4 52.025,37.2 v1(52.8,37.2)
  Signal Layer 4 w0.1: v1(51.425,41.1) 51.475,41.1 52.675,39.9 52.675,39.281 53.7,38.256 53.7,37.6 53.3,37.2 v1(52.8,37.2)
DEBUG_TCK_SWCLK_#OE: U809.A1 U900.B1 | length 6.5
  Top Layer w0.1: U900.B1@49.6,42 49.819,42 49.862,41.957 50.043,41.957 50.35,41.65 50.35,40.975 50.457,40.868 50.457,40.612 50.463,40.607 50.463,40.587 51.15,39.9 51.5,39.9 51.625,39.775 51.625,39.575 51.85,39.35 52.425,39.35 52.925,39.85 52.925,40.55 U809.A1@52.55,40.925
DEBUG_TCK_SWCLK_C2CK: J102.10 R301.1 U1.4 U805.3 | length 68.3
  Top Layer w0.1: J102.10@41.11,56.602 42.5,55.212 v1(42.5,51.5) R301.1@41.85,51.5 ; U805.3@64.775,36.185 v1@64.775,36.75 ; v1(82.575,34.175) 82.975,34.175 83.375,34.575 83.375,34.8 83.825,35.25 U1.4@84.15,35.25
  Signal Layer 3 w0.1: v1(42.5,51.5) 43.675,52.675 48.85,52.675 49.425,52.1 54.75,52.1 55.2,51.65 60.75,51.65 62.375,50.025 65.625,50.025 v1(66.522,49.128) ; v1@64.825,36.9 69.1,36.9 70,36 72.1,36 73.15,37.05 77.45,37.05 80.575,33.925 81.25,33.925 81.5,34.175 v1(82.575,34.175)
  Signal Layer 4 w0.1: v1@64.825,36.9 65.4,37.475 65.4,39.375 64.975,39.8 64.975,45.3 66.522,46.847 v1(66.522,49.128)
  other v1: 64.775,36.9
DEBUG_TCK_SWCLK_IN: U808.4 U900.N3 | length 15.7
  Top Layer w0.1: U900.N3@48.6,47.5 49.2,48.1 49.325,48.1 50.175,48.95 50.875,48.95 51.075,49.15 52.2,49.15 52.475,48.875 55.35,48.875 59.275,44.95 60.575,44.95 61.225,44.3 U808.4@61.605,44.3
DEBUG_TCK_SWCLK_OUT: U809.B1 U900.C1 | length 4.5
  Top Layer w0.1: U900.C1@49.6,42.5 49.75,42.35 v1(50.025,42.35) v1@50.05,42.325 ; U809.B1@52.55,41.425 52.713,41.263 v1(53,41.263)
  Signal Layer 3 w0.1: v1(50.025,42.35) 51.913,42.35 v1(53,41.263)
DEBUG_TDI_#OE: U809.B2 U900.E1 | length 3.5
  Top Layer w0.1: U900.E1@49.6,43.5 50.125,43.5 50.25,43.375 50.45,43.375 51.2,42.625 51.2,42.275 U809.B2@52.05,41.425
DEBUG_TDI_C2DPS: R302.2 R303.2 U805.11 | length 32.8
  Top Layer w0.1: R302.2@46.75,51.5 R303.2@47.75,51.5 v1(47.75,52.15) ; v1(64.05,38.775) 64.375,38.45 U805.11@64.375,37.955
  Signal Layer 3 w0.1: v1(47.75,52.15) 48.025,51.875 53.625,51.875 54.4,51.1 54.9,51.1 55.225,51.425 60.375,51.425 62,49.8 64.95,49.8 v1(65.375,49.375)
  Signal Layer 4 w0.1: v1(64.05,38.775) 64.05,45.425 65.375,46.75 v1(65.375,49.375)
DEBUG_TDI_IN: U808.6 U900.N4 | length 18.9
  Top Layer w0.1: U900.N4@48.1,47.5 48.461,47.861 v1(48.461,47.975) ; v1(60.675,43.3) U808.6@61.605,43.3
  Bottom Layer w0.1: v1(48.461,47.975) 49.45,47.975 50.675,49.2 52.55,49.2 53.325,48.425 54.375,48.425 60.175,42.625 60.175,42.4 60.4,42.175 60.85,42.175 61.15,42.475 61.15,42.825 v1(60.675,43.3)
DEBUG_TDI_OUT: U809.D2 U900.E2 | length 3.9
  Top Layer w0.1: U900.E2@49.1,43.5 49.35,43.75 50.194,43.75 50.362,43.582 50.543,43.582 50.925,43.2 51.725,43.2 52.05,42.875 U809.D2@52.05,42.425
DEBUG_TDO_SWO: U805.8
DEBUG_TDO_SWO_IN: U808.5 U900.E3 | length 22.1
  Top Layer w0.1: v1(46.35,45.35) 46.75,44.95 46.92,44.95 47.085,44.785 47.085,44.465 47.325,44.225 47.645,44.225 47.845,44.025 48.2,44.025 48.6,43.625 U900.E3@48.6,43.5 ; v1(60.7,43.975) 60.725,43.975 60.9,43.8 U808.5@61.605,43.8
  Signal Layer 3 w0.1: v1(46.35,45.35) 46.125,45.575 46.125,46.225 47.025,47.125 50.294,47.125 50.569,47.4 51.95,47.4 52.275,47.725 53.175,47.725 53.525,47.375 55.35,47.375 56.8,45.925 58.75,45.925 v1(60.7,43.975)
  Signal Layer 4 w0.1: v1(46.35,45.35) v1@46.431,45.35
DEBUG_TMS_SWDIO_#OE: U804.B2 U900.D2 | length 8.8
  Top Layer w0.1: U900.D2@49.1,43 49.35,43.25 49.825,43.25 49.9,43.175 50.35,43.175 51,42.525 51,41.825 v1(51.15,41.675) ; v1@50.775,37.65 51.025,37.9 U804.B2@51.325,37.9
  Bottom Layer w0.1: v1(50.825,37.65) 51.275,38.1 51.275,38.625 50.675,39.225 50.675,40.075 50.35,40.4 50.35,40.875 v1(51.15,41.675)
DEBUG_TMS_SWDIO_C2D: J102.12 R302.1 U1.5 U805.1 | length 64.5
  Top Layer w0.1: J102.12@43.65,56.602 44.925,55.327 44.925,53.075 v1(45.85,52.15) R302.1@45.85,51.5 ; U805.1@63.975,36.185 63.975,35.925 v1@64.285,35.615 ; v1(81.525,33.175) 81.95,33.6 82.8,33.6 83.575,34.375 83.575,34.5 83.825,34.75 U1.5@84.15,34.75
  Signal Layer 3 w0.1: v1(45.85,52.15) 46.35,51.65 53.55,51.65 54.625,50.575 55.875,50.575 56.4,51.1 60.175,51.1 61.775,49.5 64.525,49.5 65.3,48.725 v1(65.875,48.725) ; v1@64.407,35.479 64.921,35.993 69.307,35.993 69.7,35.6 72.294,35.6 72.469,35.775 73.025,35.775 75.625,33.175 v1(81.525,33.175)
  Signal Layer 4 w0.1: v1(64.285,35.479) 64.285,38.185 64.525,38.425 64.525,45.35 65.875,46.7 v1(65.875,48.725)
DEBUG_TMS_SWDIO_IN: U808.3 U900.M3 | length 15.4
  Top Layer w0.1: U900.M3@48.6,47 48.85,47.25 49.704,47.25 50.029,47.575 v1(50.175,47.575) ; v1(61.025,45.8) 60.875,45.65 60.875,45.125 61.2,44.8 U808.3@61.605,44.8
  Signal Layer 3 w0.1: v1(50.175,47.575) 50.4,47.8 51.925,47.8 52.175,48.05 53.15,48.05 53.6,47.6 55.5,47.6 56.925,46.175 60.65,46.175 v1(61.025,45.8)
DEBUG_TMS_SWDIO_OUT: U804.D2 U900.C2 | length 5
  Top Layer w0.1: U900.C2@49.1,42.5 49.35,42.25 49.35,41.9 49.35,41.896 49.496,41.75 49.925,41.75 50.1,41.575 50.1,40.925 50.25,40.775 50.25,40.45 50.675,40.025 50.675,39.225 51,38.9 U804.D2@51.325,38.9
